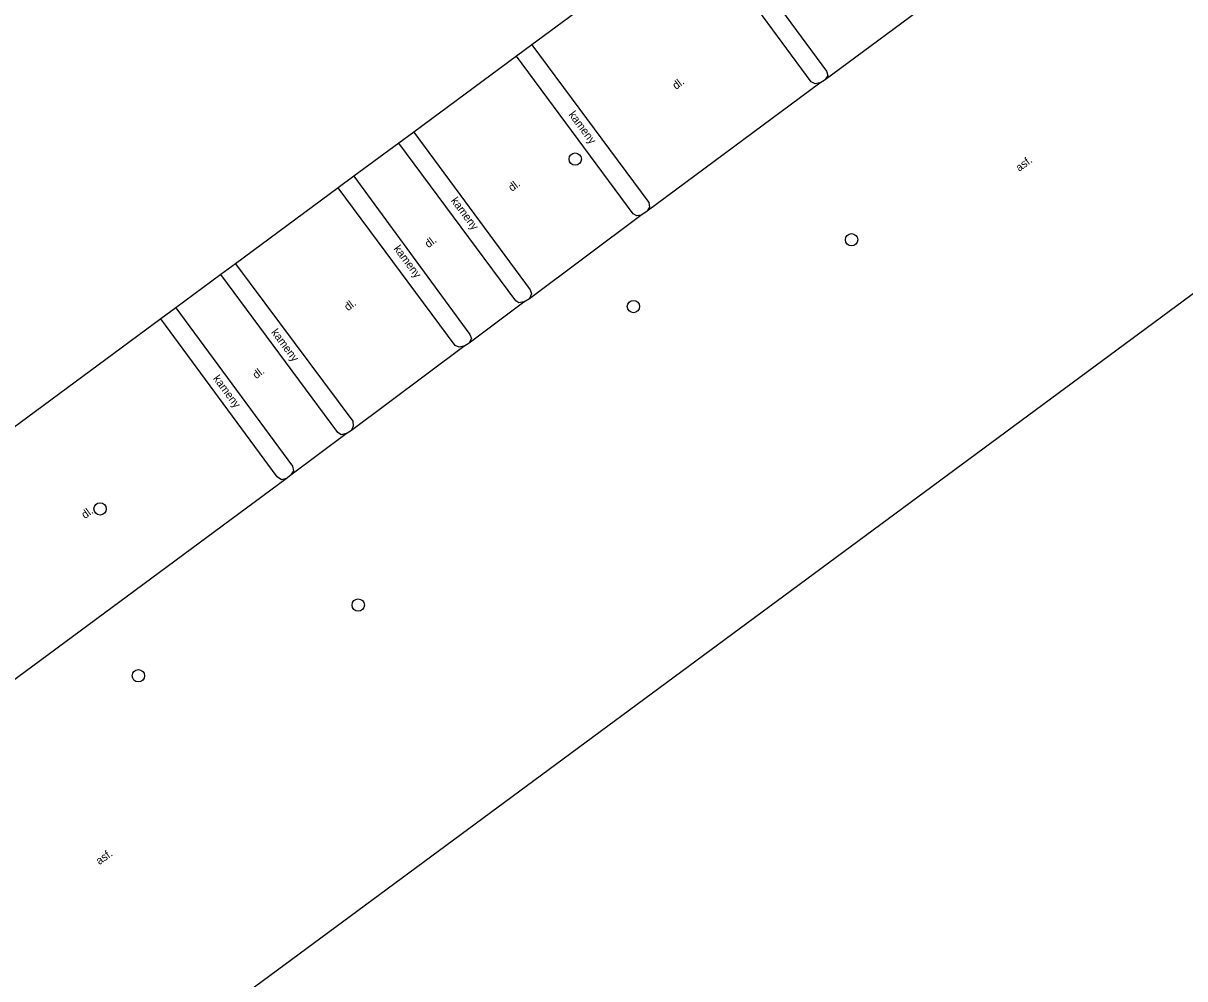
# Model space of a CAD drawing. Extents: x -596024 to -594475, y -1163820 to -1161957.
# Drawn here: x -594798.2 to -594703.9, y -1162768.8 to -1162691.2 of the extents above; entities that cross this region are included whole.
import ezdxf

# ---------------------------------------------------------------- set-up
doc = ezdxf.new("R2010")
doc.units = 0
for name, color, linetype in [('Level 10', 7, 'Continuous'), ('Level 11', 7, 'Continuous'), ('Level 27', 7, 'Continuous'), ('Level 40', 7, 'Continuous'), ('Level 5', 7, 'Continuous')]:
    doc.layers.add(name, color=color, linetype=linetype)

msp = doc.modelspace()

# ---------------------------------------------------------------- linework, layer by layer
at = {"layer": 'Level 10'}
for points in [[(-594742.42, -1162682.3), (-594732.95, -1162695.12), (-594732.85, -1162695.48)], [(-594733.87, -1162696.15), (-594734.2, -1162695.99), (-594743.63, -1162683.19)], [(-594756.89, -1162692.99), (-594747.4, -1162705.8), (-594747.35, -1162706.18)], [(-594748.37, -1162706.88), (-594748.67, -1162706.72), (-594758.15, -1162693.92)], [(-594732.85, -1162695.48), (-594733.07, -1162695.82)], [(-594733.51, -1162696.07), (-594733.87, -1162696.15)], [(-594733.51, -1162696.07), (-594733.07, -1162695.82)], [(-594766.49, -1162700.08), (-594757.02, -1162712.9), (-594756.93, -1162713.23)], [(-594757.94, -1162713.96), (-594758.2, -1162713.79), (-594767.71, -1162700.98)], [(-594771.36, -1162703.67), (-594761.93, -1162716.51), (-594761.81, -1162716.84)], [(-594762.8, -1162717.56), (-594763.12, -1162717.4), (-594772.63, -1162704.61)], [(-594748.04, -1162706.84), (-594748.37, -1162706.88)], [(-594748.04, -1162706.84), (-594747.53, -1162706.47)], [(-594747.35, -1162706.18), (-594747.53, -1162706.47)], [(-594772.38, -1162724.66), (-594772.66, -1162724.48), (-594782.17, -1162711.66)], [(-594780.96, -1162710.77), (-594771.45, -1162723.57), (-594771.4, -1162723.97)], [(-594756.93, -1162713.23), (-594757.1, -1162713.6)], [(-594785.81, -1162714.35), (-594776.35, -1162727.2), (-594776.25, -1162727.58)], [(-594757.55, -1162713.87), (-594757.94, -1162713.96)], [(-594757.55, -1162713.87), (-594757.1, -1162713.6)], [(-594777.24, -1162728.32), (-594777.58, -1162728.09), (-594787.04, -1162715.26)], [(-594762.41, -1162717.47), (-594762, -1162717.19)], [(-594761.81, -1162716.84), (-594762, -1162717.19)], [(-594762.41, -1162717.47), (-594762.8, -1162717.56)], [(-594771.99, -1162724.56), (-594772.38, -1162724.66)], [(-594771.99, -1162724.56), (-594771.54, -1162724.3)], [(-594771.4, -1162723.97), (-594771.54, -1162724.3)], [(-594776.25, -1162727.58), (-594776.46, -1162727.92)], [(-594776.85, -1162728.21), (-594777.24, -1162728.32)], [(-594776.85, -1162728.21), (-594776.46, -1162727.92)]]:
    msp.add_lwpolyline(points, dxfattribs=at)
at = {"layer": 'Level 11'}
for points in [[(-594733.07, -1162695.82), (-594723.72, -1162688.88)], [(-594747.53, -1162706.47), (-594733.51, -1162696.07)], [(-594757.1, -1162713.6), (-594748.04, -1162706.84)], [(-594762, -1162717.19), (-594757.55, -1162713.87)], [(-594771.54, -1162724.3), (-594762.41, -1162717.47)], [(-594776.46, -1162727.92), (-594771.99, -1162724.56)], [(-594800.67, -1162745.8), (-594776.85, -1162728.21)]]:
    msp.add_lwpolyline(points, dxfattribs=at)
at = {"layer": 'Level 27'}
for centre in [(-594753.37, -1162702.27), (-594730.93, -1162708.82), (-594748.64, -1162714.25), (-594791.97, -1162730.68), (-594771, -1162738.49), (-594788.86, -1162744.23)]:
    msp.add_circle(centre, 0.5, dxfattribs=at)
at = {"layer": 'Level 5'}
for points in [[(-594743.63, -1162683.19), (-594756.89, -1162692.99), (-594758.15, -1162693.92), (-594766.49, -1162700.08), (-594767.71, -1162700.98), (-594771.36, -1162703.67), (-594772.63, -1162704.61), (-594780.96, -1162710.77), (-594782.17, -1162711.66), (-594785.81, -1162714.35), (-594787.04, -1162715.26), (-594809.91, -1162732.15), (-594811.13, -1162733.05), (-594819.55, -1162739.27), (-594820.75, -1162740.16), (-594838.58, -1162753.33), (-594839.86, -1162754.27)], [(-594741.2, -1162741.26), (-594700.35, -1162711.11)], [(-594845.04, -1162817.92), (-594741.2, -1162741.26)]]:
    msp.add_lwpolyline(points, dxfattribs=at)

# ---------------------------------------------------------------- texts
at = {"layer": 'Level 40'}
for s, rotation, p in [('dl.', 37, (-594745.18, -1162696.66)), ('kameny', 306.54395, (-594753.94, -1162698.67)), ('asf.', 37, (-594717.3, -1162703.32)), ('dl.', 37, (-594758.51, -1162704.94)), ('kameny', 306.5889, (-594763.5, -1162705.66)), ('dl.', 37, (-594765.3, -1162709.52)), ('kameny', 306.63038, (-594768.15, -1162709.56)), ('dl.', 37, (-594771.84, -1162714.64)), ('kameny', 306.59634, (-594778.1, -1162716.35)), ('kameny', 306.37977, (-594782.82, -1162720.1)), ('dl.', 37, (-594779.28, -1162720.16)), ('dl.', 36, (-594793.2, -1162731.52)), ('asf.', 36, (-594792.02, -1162759.62))]:
    msp.add_text(s, height=0.65, rotation=rotation, dxfattribs=at).set_placement(p)

doc.saveas('drawing.dxf')
